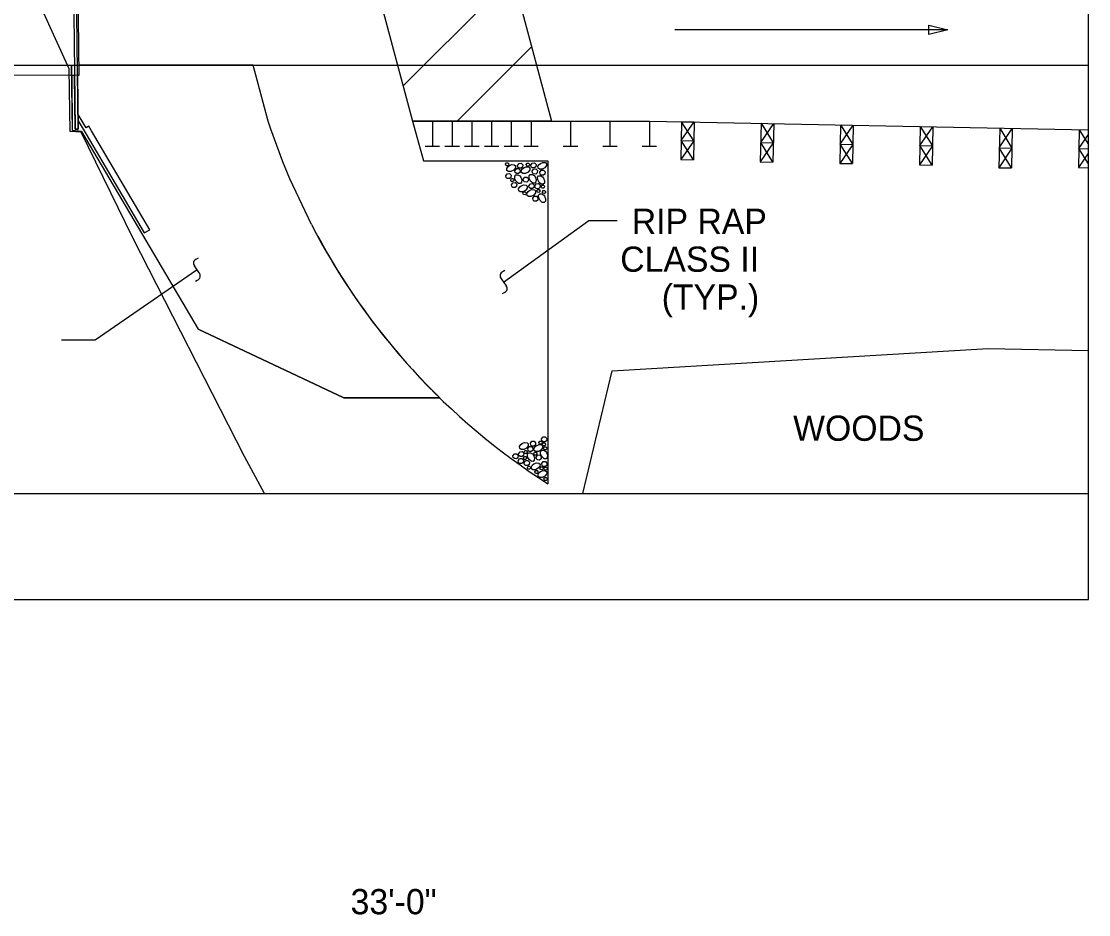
# Model space of a CAD drawing. Extents: x 471 to 2034, y -623 to 126.
# Drawn here: x 720.8 to 805.3, y -364.8 to -294.1 of the extents above; entities that cross this region are included whole.
import ezdxf

# ---------------------------------------------------------------- set-up
doc = ezdxf.new("R2010")
doc.units = 0
for name, color, linetype in [('Arrowhead Terminators CELL', 7, 'Continuous'), ('Default', 7, 'Continuous'), ('Dimension Lines', 7, 'Continuous'), ('Exist Hydro Stream or Body of Water', 7, 'Continuous'), ('Exist Structure Major Deck Tunnel Box Culvert', 7, 'Continuous'), ('Exist Vegetation Woods Line', 7, 'Continuous'), ('Mis Object Lines', 7, 'Continuous'), ('Miscellaneous Lines CELL', 7, 'Continuous'), ('Plan Sheet CELL', 7, 'Continuous'), ('Prop EOT', 7, 'Continuous'), ('Sup Concrete Girder Lines', 7, 'Continuous'), ('Text', 7, 'Continuous')]:
    doc.layers.add(name, color=color, linetype=linetype)

msp = doc.modelspace()

# ---------------------------------------------------------------- linework, layer by layer
at = {"layer": 'Arrowhead Terminators CELL'}
for p, q in [((734.865, -314.001), (734.489, -313.456)), ((734.628, -312.935), (734.824, -312.834)), ((759.081, -313.832), (758.933, -313.904)), ((734.572, -314.666), (734.721, -314.597)), ((758.801, -314.503), (759.188, -315.04)), ((759.061, -315.564), (758.867, -315.669))]:
    msp.add_line(p, q, dxfattribs=at)
msp.add_lwpolyline([(794.168, -294.768), (792.668, -295.143), (792.668, -294.393)], close=True, dxfattribs=at)
msp.add_lwpolyline([(794.168, -294.768), (792.668, -295.143), (792.668, -294.393)], close=True, dxfattribs=at)
for centre, radius, start, end in [((734.744, -313.247), 0.331, 110.38616, 218.67174), ((734.585, -314.246), 0.373, 291.31771, 41.11659), ((759.077, -314.252), 0.373, 112.5062, 222.30507), ((758.938, -315.254), 0.331, 291.57464, 39.86022)]:
    msp.add_arc(centre, radius, start, end, dxfattribs=at)
at = {"layer": 'Default'}
for p, q in [((724.765, -297.575), (724.977, -297.575)), ((724.765, -297.575), (724.804, -302.738)), ((724.986, -298.373), (724.771, -298.372)), ((724.771, -298.372), (724.804, -302.738)), ((739.14, -297.575), (725.327, -297.575)), ((725.327, -297.575), (739.14, -297.575)), ((740.323, -301.992), (739.14, -297.575)), ((751.775, -301.992), (770.525, -301.992)), ((753.338, -301.992), (753.338, -303.992)), ((754.9, -301.992), (754.9, -303.992)), ((756.463, -301.992), (756.463, -303.992)), ((758.025, -301.992), (758.025, -303.992)), ((759.588, -301.992), (759.588, -303.992)), ((761.15, -301.992), (761.15, -303.992)), ((764.275, -301.992), (764.275, -303.992)), ((767.4, -301.992), (767.4, -303.992)), ((770.525, -301.992), (770.525, -303.992)), ((770.525, -301.992), (805.312, -302.688)), ((773.067, -302.043), (773.007, -305.042)), ((773.037, -303.543), (774.067, -302.063)), ((773.067, -302.043), (774.067, -302.063)), ((774.037, -303.563), (773.067, -302.043)), ((774.067, -302.063), (774.007, -305.062)), ((774.067, -302.063), (774.037, -303.563)), ((779.367, -302.169), (779.306, -305.221)), ((779.337, -303.695), (780.367, -302.189)), ((779.367, -302.169), (780.337, -303.715)), ((780.367, -302.189), (780.306, -305.241)), ((785.667, -302.295), (785.606, -305.342)), ((785.637, -303.819), (786.667, -302.315)), ((785.667, -302.295), (786.637, -303.839)), ((786.667, -302.315), (786.606, -305.362)), ((791.967, -302.421), (791.906, -305.456)), ((791.937, -303.939), (792.967, -302.441)), ((791.967, -302.421), (792.967, -302.441)), ((791.967, -302.421), (792.937, -303.959)), ((792.967, -302.441), (792.906, -305.476)), ((798.267, -302.547), (798.204, -305.684)), ((798.235, -304.115), (799.267, -302.567)), ((798.267, -302.547), (799.235, -304.135)), ((799.267, -302.567), (799.204, -305.704)), ((725.538, -302.812), (724.804, -302.738)), ((725.538, -302.812), (734.795, -318.472)), ((804.567, -302.673), (804.507, -305.672)), ((804.537, -304.173), (805.312, -303.059)), ((804.567, -302.673), (805.312, -303.841)), ((752.765, -303.992), (753.91, -303.992)), ((754.327, -303.992), (755.473, -303.992)), ((755.89, -303.992), (757.035, -303.992)), ((757.452, -303.992), (758.598, -303.992)), ((759.015, -303.992), (760.16, -303.992)), ((760.577, -303.992), (761.723, -303.992)), ((763.702, -303.992), (764.848, -303.992)), ((766.827, -303.992), (767.973, -303.992)), ((769.952, -303.992), (771.098, -303.992)), ((774.037, -303.563), (773.007, -305.042)), ((773.037, -303.543), (774.037, -303.563)), ((774.007, -305.062), (773.037, -303.543)), ((780.337, -303.715), (779.306, -305.221)), ((779.337, -303.695), (780.337, -303.715)), ((780.306, -305.241), (779.337, -303.695)), ((786.637, -303.839), (785.606, -305.342)), ((785.637, -303.819), (786.637, -303.839)), ((786.606, -305.362), (785.637, -303.819)), ((792.937, -303.959), (791.906, -305.456)), ((791.937, -303.939), (792.937, -303.959)), ((792.906, -305.476), (791.937, -303.939)), ((799.235, -304.135), (798.204, -305.684)), ((798.235, -304.115), (799.235, -304.135)), ((799.204, -305.704), (798.235, -304.115)), ((804.537, -304.173), (805.312, -304.188)), ((805.312, -305.387), (804.537, -304.173)), ((773.007, -305.042), (774.007, -305.062)), ((805.312, -304.515), (804.507, -305.672)), ((779.306, -305.221), (780.306, -305.241)), ((785.606, -305.342), (786.606, -305.362)), ((791.906, -305.456), (792.906, -305.476)), ((798.204, -305.684), (799.204, -305.704)), ((804.507, -305.672), (805.312, -305.688)), ((746.318, -323.908), (734.795, -318.472)), ((753.918, -323.908), (746.318, -323.908)), ((746.318, -323.908), (753.918, -323.908))]:
    msp.add_line(p, q, dxfattribs=at)
for points in [[(724.734, -297.575), (724.804, -302.738), (725.538, -302.812), (734.795, -318.472), (746.318, -323.908), (753.918, -323.908)], [(725.236, -298.373), (725.284, -302.625), (725.034, -302.628), (724.986, -298.373)], [(725.327, -297.575), (725.336, -298.373), (725.236, -298.373)], [(743.758, -310.172), (742.038, -306.557), (741.487, -305.223), (740.537, -302.638), (740.323, -301.992)], [(724.804, -302.738), (725.538, -302.812), (734.795, -318.472), (746.318, -323.908)]]:
    msp.add_lwpolyline(points, dxfattribs=at)
msp.add_arc((791.286, -285.644), 53.484, 207.29694, 225.6782, dxfattribs=at)
at = {"layer": 'Dimension Lines'}
for p, q in [((794.168, -294.768), (772.549, -294.768)), ((758.962, -314.739), (765.737, -309.863)), ((765.737, -309.863), (767.965, -309.863)), ((734.709, -313.762), (726.619, -319.333)), ((726.619, -319.333), (723.965, -319.333))]:
    msp.add_line(p, q, dxfattribs=at)
at = {"layer": 'Exist Hydro Stream or Body of Water'}
msp.add_lwpolyline([(740.035, -331.475), (738.449, -328.551), (729.624, -311.241), (725.511, -302.868), (724.663, -302.806), (724.567, -297.853), (717.841, -283.089), (718.312, -273.628), (719.049, -271.765)], dxfattribs=at)
at = {"layer": 'Exist Structure Major Deck Tunnel Box Culvert'}
for points in [[(724.923, -270.707), (724.673, -270.71), (725.034, -302.628), (725.284, -302.625), (724.923, -270.707)], [(672.416, -290.713), (672.364, -285.978), (672.254, -276.061), (672.238, -274.603), (690.237, -274.64), (707.125, -274.674), (725.068, -274.71), (725.087, -276.371), (725.2, -286.374), (725.311, -296.196), (725.336, -298.373), (707.383, -298.337), (690.429, -298.303), (672.5, -298.266)], [(725.296, -301.967), (725.918, -303.025), (730.517, -310.85), (730.948, -310.596), (726.349, -302.771), (726.127, -302.394), (725.912, -302.521), (725.29, -301.463), (725.296, -301.967)]]:
    msp.add_lwpolyline(points, dxfattribs=at)
at = {"layer": 'Exist Vegetation Woods Line'}
msp.add_lwpolyline([(765.24, -331.475), (767.569, -321.763), (797.362, -320.012), (805.312, -320.159)], dxfattribs=at)
at = {"layer": 'Mis Object Lines'}
for p, q in [((743.513, -271.159), (751.775, -301.992)), ((754.513, -271.159), (762.775, -301.992)), ((751.027, -299.2), (759.702, -290.525)), ((755.306, -301.992), (761.197, -296.101)), ((762.775, -301.992), (751.775, -301.992))]:
    msp.add_line(p, q, dxfattribs=at)
at = {"layer": 'Miscellaneous Lines CELL'}
for points in [[(759.134, -305.396), (759.201, -305.3), (759.308, -305.294), (759.383, -305.371), (759.372, -305.48), (759.306, -305.535), (759.2, -305.527), (759.15, -305.479), (759.134, -305.396)], [(759.424, -305.519), (759.634, -305.435), (759.826, -305.452), (759.918, -305.539), (759.915, -305.695), (759.776, -305.873), (759.561, -305.98), (759.359, -305.984), (759.245, -305.903), (759.234, -305.742), (759.327, -305.598), (759.433, -305.513)], [(759.877, -305.92), (759.989, -305.76), (760.168, -305.75), (760.292, -305.879), (760.274, -306.06), (760.164, -306.152), (759.987, -306.139), (759.904, -306.058), (759.877, -305.92)], [(760.088, -305.498), (760.2, -305.339), (760.379, -305.328), (760.503, -305.457), (760.485, -305.638), (760.375, -305.73), (760.198, -305.717), (760.115, -305.637), (760.088, -305.498)], [(760.563, -305.688), (760.773, -305.605), (760.965, -305.621), (761.057, -305.709), (761.054, -305.865), (760.915, -306.042), (760.7, -306.15), (760.498, -306.153), (760.384, -306.072), (760.373, -305.911), (760.466, -305.767), (760.571, -305.683)], [(760.768, -305.433), (760.835, -305.337), (760.942, -305.331), (761.017, -305.408), (761.006, -305.517), (760.94, -305.572), (760.834, -305.564), (760.784, -305.516), (760.768, -305.433)], [(761.135, -305.474), (761.247, -305.314), (761.426, -305.304), (761.55, -305.433), (761.532, -305.614), (761.422, -305.706), (761.245, -305.693), (761.162, -305.612), (761.135, -305.474)], [(761.24, -305.951), (761.353, -305.792), (761.531, -305.781), (761.656, -305.91), (761.638, -306.091), (761.527, -306.183), (761.351, -306.17), (761.268, -306.09), (761.241, -305.951)], [(761.887, -305.346), (762.097, -305.263), (762.289, -305.28), (762.381, -305.367), (762.378, -305.523), (762.239, -305.701), (762.024, -305.808), (761.822, -305.812), (761.708, -305.731), (761.697, -305.57), (761.79, -305.425), (761.895, -305.341)], [(761.853, -306.049), (761.965, -305.889), (762.144, -305.879), (762.268, -306.008), (762.25, -306.189), (762.14, -306.281), (761.963, -306.268), (761.88, -306.187), (761.853, -306.049)], [(759.159, -306.32), (759.271, -306.16), (759.45, -306.15), (759.574, -306.279), (759.556, -306.46), (759.445, -306.552), (759.269, -306.539), (759.186, -306.458), (759.159, -306.32)], [(759.544, -306.646), (759.611, -306.551), (759.718, -306.544), (759.793, -306.622), (759.782, -306.73), (759.716, -306.785), (759.61, -306.778), (759.56, -306.729), (759.544, -306.646)], [(760.335, -306.432), (760.418, -306.642), (760.401, -306.834), (760.314, -306.926), (760.158, -306.923), (759.981, -306.784), (759.873, -306.569), (759.87, -306.367), (759.951, -306.253), (760.112, -306.242), (760.256, -306.335), (760.34, -306.441)], [(760.536, -306.591), (760.648, -306.431), (760.827, -306.421), (760.951, -306.55), (760.933, -306.731), (760.823, -306.823), (760.646, -306.81), (760.563, -306.729), (760.536, -306.591)], [(761.474, -306.405), (761.557, -306.615), (761.54, -306.807), (761.453, -306.899), (761.297, -306.896), (761.119, -306.757), (761.012, -306.542), (761.008, -306.34), (761.089, -306.226), (761.25, -306.215), (761.395, -306.308), (761.479, -306.414)], [(762.138, -306.507), (762.221, -306.716), (762.204, -306.909), (762.117, -307), (761.961, -306.998), (761.784, -306.859), (761.676, -306.644), (761.673, -306.442), (761.754, -306.328), (761.915, -306.317), (762.059, -306.409), (762.143, -306.515)], [(759.601, -307.031), (759.713, -306.872), (759.892, -306.862), (760.016, -306.991), (759.998, -307.171), (759.888, -307.263), (759.711, -307.251), (759.628, -307.17), (759.601, -307.031)], [(760.36, -307.125), (760.569, -307.042), (760.762, -307.058), (760.853, -307.146), (760.85, -307.302), (760.711, -307.479), (760.497, -307.587), (760.294, -307.59), (760.181, -307.509), (760.17, -307.348), (760.262, -307.204), (760.368, -307.12)], [(760.51, -307.687), (760.578, -307.591), (760.685, -307.585), (760.76, -307.662), (760.749, -307.771), (760.683, -307.826), (760.577, -307.818), (760.527, -307.77), (760.51, -307.687)], [(761.01, -307.499), (761.219, -307.416), (761.412, -307.433), (761.504, -307.52), (761.501, -307.676), (761.362, -307.854), (761.147, -307.961), (760.945, -307.965), (760.831, -307.884), (760.82, -307.723), (760.913, -307.578), (761.018, -307.494)], [(760.985, -307.11), (761.097, -306.951), (761.276, -306.941), (761.4, -307.07), (761.382, -307.25), (761.271, -307.342), (761.095, -307.33), (761.012, -307.249), (760.985, -307.11)], [(761.445, -307.117), (761.558, -306.958), (761.736, -306.948), (761.861, -307.076), (761.843, -307.257), (761.732, -307.349), (761.556, -307.336), (761.473, -307.256), (761.446, -307.117)], [(761.609, -307.503), (761.676, -307.407), (761.783, -307.401), (761.858, -307.478), (761.847, -307.587), (761.781, -307.642), (761.675, -307.634), (761.625, -307.586), (761.609, -307.503)], [(761.955, -307.166), (762.023, -307.071), (762.13, -307.065), (762.204, -307.142), (762.194, -307.25), (762.127, -307.306), (762.021, -307.298), (761.972, -307.25), (761.955, -307.166)], [(762.05, -307.581), (762.117, -307.486), (762.224, -307.48), (762.299, -307.557), (762.288, -307.665), (762.222, -307.721), (762.116, -307.713), (762.066, -307.665), (762.05, -307.582)], [(761.284, -308.108), (761.396, -307.948), (761.575, -307.938), (761.7, -308.067), (761.682, -308.248), (761.571, -308.34), (761.395, -308.327), (761.311, -308.246), (761.285, -308.108)], [(762.219, -307.937), (762.302, -308.147), (762.286, -308.339), (762.199, -308.431), (762.042, -308.428), (761.865, -308.289), (761.758, -308.074), (761.754, -307.872), (761.835, -307.758), (761.996, -307.747), (762.14, -307.84), (762.225, -307.945)], [(761.989, -327.164), (762.101, -327.005), (762.28, -326.995), (762.404, -327.124), (762.386, -327.305), (762.276, -327.396), (762.099, -327.384), (762.016, -327.303), (761.989, -327.165)], [(760.434, -327.529), (760.643, -327.446), (760.836, -327.463), (760.927, -327.55), (760.925, -327.706), (760.786, -327.884), (760.571, -327.991), (760.369, -327.995), (760.255, -327.914), (760.244, -327.753), (760.336, -327.608), (760.442, -327.524)], [(760.887, -327.931), (760.999, -327.771), (761.178, -327.761), (761.302, -327.89), (761.284, -328.071), (761.174, -328.163), (760.997, -328.15), (760.914, -328.069), (760.887, -327.931)], [(761.098, -327.509), (761.21, -327.35), (761.389, -327.339), (761.513, -327.468), (761.495, -327.649), (761.384, -327.741), (761.208, -327.728), (761.125, -327.648), (761.098, -327.509)], [(761.572, -327.699), (761.782, -327.616), (761.975, -327.632), (762.066, -327.719), (762.063, -327.876), (761.924, -328.053), (761.71, -328.161), (761.507, -328.164), (761.394, -328.083), (761.383, -327.922), (761.475, -327.778), (761.581, -327.694)], [(761.777, -327.443), (761.845, -327.348), (761.952, -327.342), (762.027, -327.419), (762.016, -327.527), (761.95, -327.583), (761.844, -327.575), (761.794, -327.527), (761.777, -327.444)], [(762.048, -327.567), (762.115, -327.471), (762.223, -327.465), (762.297, -327.542), (762.286, -327.651), (762.22, -327.706), (762.114, -327.698), (762.064, -327.65), (762.048, -327.567)], [(762.147, -327.884), (762.214, -327.789), (762.321, -327.783), (762.396, -327.86), (762.385, -327.968), (762.319, -328.024), (762.213, -328.016), (762.163, -327.968), (762.147, -327.884)], [(759.721, -328.506), (759.833, -328.346), (760.012, -328.336), (760.136, -328.465), (760.118, -328.646), (760.007, -328.738), (759.831, -328.725), (759.748, -328.644), (759.721, -328.506)], [(760.137, -328.884), (760.249, -328.725), (760.428, -328.714), (760.552, -328.843), (760.534, -329.024), (760.424, -329.116), (760.247, -329.103), (760.164, -329.023), (760.137, -328.884)], [(760.168, -328.331), (760.28, -328.171), (760.459, -328.161), (760.584, -328.29), (760.566, -328.471), (760.455, -328.563), (760.278, -328.55), (760.195, -328.469), (760.168, -328.331)], [(760.553, -328.657), (760.62, -328.562), (760.728, -328.555), (760.802, -328.633), (760.792, -328.741), (760.725, -328.796), (760.619, -328.789), (760.569, -328.74), (760.553, -328.657)], [(760.601, -328.173), (760.669, -328.077), (760.776, -328.071), (760.851, -328.148), (760.84, -328.257), (760.774, -328.312), (760.668, -328.304), (760.618, -328.256), (760.602, -328.173)], [(761.344, -328.443), (761.428, -328.653), (761.411, -328.845), (761.324, -328.937), (761.168, -328.934), (760.99, -328.795), (760.883, -328.58), (760.879, -328.378), (760.96, -328.264), (761.121, -328.253), (761.265, -328.346), (761.35, -328.452)], [(761.369, -328.306), (761.437, -328.21), (761.544, -328.204), (761.618, -328.282), (761.608, -328.39), (761.541, -328.445), (761.435, -328.437), (761.386, -328.389), (761.369, -328.306)], [(761.546, -328.602), (761.658, -328.442), (761.837, -328.432), (761.961, -328.561), (761.943, -328.742), (761.833, -328.834), (761.656, -328.821), (761.573, -328.74), (761.546, -328.602)], [(762.375, -328.238), (762.458, -328.447), (762.441, -328.64), (762.354, -328.731), (762.198, -328.728), (762.02, -328.589), (761.913, -328.375), (761.909, -328.172), (761.99, -328.059), (762.152, -328.048), (762.296, -328.14), (762.38, -328.246)], [(760.61, -329.042), (760.722, -328.883), (760.901, -328.873), (761.026, -329.002), (761.008, -329.182), (760.897, -329.274), (760.72, -329.261), (760.637, -329.181), (760.61, -329.042)], [(760.86, -329.421), (760.928, -329.325), (761.035, -329.319), (761.11, -329.397), (761.099, -329.505), (761.033, -329.56), (760.927, -329.552), (760.877, -329.504), (760.861, -329.421)], [(761.369, -329.136), (761.579, -329.053), (761.771, -329.069), (761.863, -329.156), (761.86, -329.313), (761.721, -329.49), (761.506, -329.598), (761.304, -329.601), (761.19, -329.52), (761.179, -329.359), (761.272, -329.215), (761.378, -329.131)], [(761.861, -329.461), (761.929, -329.365), (762.036, -329.359), (762.111, -329.437), (762.1, -329.545), (762.033, -329.6), (761.927, -329.592), (761.878, -329.544), (761.861, -329.461)], [(761.994, -329.121), (762.106, -328.962), (762.285, -328.952), (762.409, -329.081), (762.391, -329.261), (762.281, -329.353), (762.104, -329.34), (762.021, -329.26), (761.994, -329.121)], [(762.176, -329.499), (762.243, -329.404), (762.35, -329.398), (762.425, -329.475), (762.414, -329.583), (762.348, -329.639), (762.242, -329.631), (762.192, -329.582), (762.176, -329.499)], [(761.451, -329.77), (761.518, -329.674), (761.625, -329.668), (761.7, -329.745), (761.689, -329.854), (761.623, -329.909), (761.517, -329.901), (761.467, -329.853), (761.451, -329.77)], [(761.904, -329.745), (762.114, -329.662), (762.306, -329.678), (762.398, -329.765), (762.395, -329.921), (762.256, -330.099), (762.041, -330.206), (761.839, -330.21), (761.725, -330.129), (761.714, -329.968), (761.807, -329.824), (761.913, -329.739)], [(762.176, -330.315), (762.243, -330.219), (762.35, -330.213), (762.425, -330.291), (762.414, -330.399), (762.348, -330.454), (762.242, -330.446), (762.192, -330.398), (762.176, -330.315)]]:
    msp.add_lwpolyline(points, dxfattribs=at)
at = {"layer": 'Plan Sheet CELL'}
msp.add_line((564.339, -331.475), (805.312, -331.475), dxfattribs=at)
msp.add_lwpolyline([(564.339, -339.883), (805.312, -339.883), (805.312, -229.69)], dxfattribs=at)
at = {"layer": 'Prop EOT'}
msp.add_line((564.339, -297.575), (805.312, -297.575), dxfattribs=at)
at = {"layer": 'Sup Concrete Girder Lines'}
for p, q in [((740.323, -301.992), (739.14, -297.575)), ((751.775, -301.992), (752.621, -305.149)), ((752.621, -305.149), (762.477, -305.149)), ((762.477, -305.149), (762.477, -330.706)), ((762.775, -330.794), (762.775, -330.794))]:
    msp.add_line(p, q, dxfattribs=at)
msp.add_lwpolyline([(743.758, -310.172), (742.038, -306.557), (741.487, -305.223), (740.537, -302.638), (740.323, -301.992)], dxfattribs=at)
msp.add_arc((791.286, -285.644), 53.484, 207.29694, 237.40766, dxfattribs=at)

# ---------------------------------------------------------------- texts
at = {"layer": 'Text'}
for s, p in [('RIP RAP', (769.129, -310.928)), ('CLASS II', (768.215, -313.928)), ('(TYP.)', (771.498, -316.928)), ('WOODS', (781.907, -327.312)), ('33\'-0"', (746.861, -364.805))]:
    msp.add_text(s, height=2, dxfattribs=at).set_placement(p)

doc.saveas('drawing.dxf')
